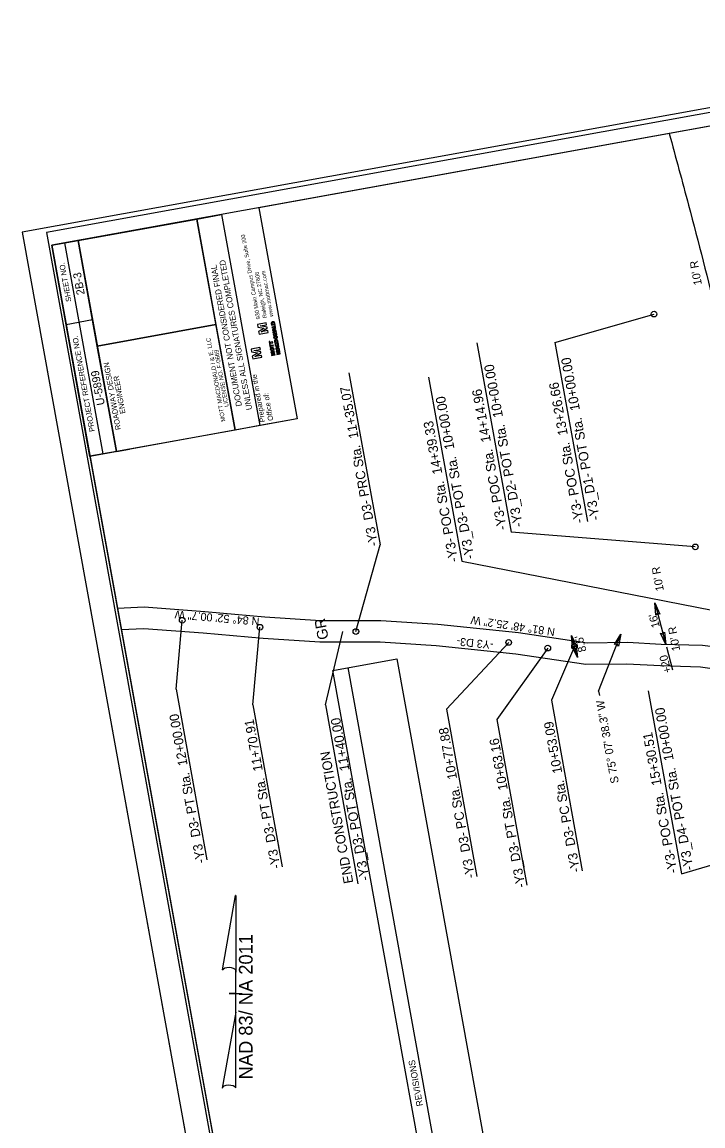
# Model space of a CAD drawing. Extents: x 1620652 to 1621205, y 897765 to 898506.
# Drawn here: x 1620651.7 to 1620905.7, y 898094.1 to 898506 of the extents above; entities that cross this region are included whole.
import ezdxf

# ---------------------------------------------------------------- set-up
doc = ezdxf.new("R2010")
doc.units = 0
for name, color, linetype in [('Exist Roads EOP', 7, 'Continuous'), ('Exist Roads Soil', 7, 'Continuous'), ('Exist Roads Soil Text', 7, 'Continuous'), ('Old_Level_2', 7, 'Continuous'), ('Old_Level_42', 7, 'Continuous'), ('Old_Level_45', 7, 'Continuous'), ('Prop Dimension', 7, 'Continuous'), ('Prop Horizontal Alignment Direction Label', 7, 'Continuous'), ('Prop Horizontal Alignment Station Label', 7, 'Continuous'), ('Prop North Arrow NAD83 for Plan Sheets CELL', 7, 'Continuous'), ('Prop Terminator CELL', 7, 'Continuous'), ('Sheet Block Revision CELL', 7, 'Continuous'), ('Sheet Cutting Line CELL', 7, 'Continuous'), ('Sheet Data Field CELL', 7, 'Continuous'), ('Sheet Layout Plan Border', 7, 'Continuous'), ('Sheet Plan CELL', 7, 'Continuous'), ('Sheet Plot Border Inside CELL', 7, 'Continuous'), ('Sheet Plot Border Outside CELL', 7, 'Continuous'), ('Sheet Sticker Exception Certification CELL', 7, 'Continuous'), ('Sheet Typical CELL', 7, 'Continuous')]:
    doc.layers.add(name, color=color, linetype=linetype)

msp = doc.modelspace()

# ---------------------------------------------------------------- linework, layer by layer
at = {"layer": 'Exist Roads EOP'}
msp.add_spline([(1620893.15, 898464.37), (1620900.36, 898437.64), (1620911.06, 898395.8), (1620918.06, 898367.23), (1620924.24, 898343.43), (1620931.2, 898316.86), (1620938.69, 898288.18), (1620945.98, 898261.48)], degree=3, dxfattribs=at)
at = {"layer": 'Exist Roads Soil'}
for points in [[(1620806.8, 898281.21), (1620785.61, 898282.63), (1620763.04, 898282.63), (1620742.29, 898283.91), (1620719.96, 898285.95), (1620697.28, 898287.65), (1620687.31, 898287.2)], [(1620806.27, 898273.23), (1620785.34, 898274.63), (1620762.79, 898274.63), (1620741.68, 898275.94), (1620719.3, 898277.98), (1620697.17, 898279.64), (1620688.75, 898279.25)], [(1620919.58, 898271.57), (1620905.51, 898273.32), (1620890.18, 898273.76), (1620877.53, 898274.44), (1620862.54, 898274.26), (1620836.86, 898278.11), (1620806.8, 898281.21)], [(1620918.02, 898263.47), (1620904.84, 898265.34), (1620889.85, 898265.76), (1620877.36, 898266.43), (1620861.99, 898266.26), (1620835.87, 898270.17), (1620806.27, 898273.23)]]:
    msp.add_lwpolyline(points, dxfattribs=at)
at = {"layer": 'Old_Level_2'}
for p, q in [((1620742.85, 898393.75), (1620739.5, 898393.15)), ((1620739.5, 898393.15), (1620739.68, 898392.15)), ((1620739.68, 898392.15), (1620741.89, 898391.72)), ((1620741.9, 898391.7), (1620739.98, 898390.52)), ((1620740.56, 898392.61), (1620742.97, 898393.05)), ((1620740.56, 898392.6), (1620740.56, 898392.61)), ((1620743.15, 898392.09), (1620740.56, 898392.6)), ((1620740.97, 898390.41), (1620743.2, 898391.79)), ((1620743.37, 898390.84), (1620740.97, 898390.4)), ((1620741.89, 898391.72), (1620741.92, 898391.73)), ((1620741.93, 898391.7), (1620741.9, 898391.7)), ((1620741.92, 898391.73), (1620741.93, 898391.7)), ((1620742.97, 898393.05), (1620742.85, 898393.75)), ((1620743.2, 898391.79), (1620743.15, 898392.09)), ((1620743.5, 898390.13), (1620743.37, 898390.84)), ((1620744.71, 898393.43), (1620744.82, 898392.85)), ((1620744.82, 898392.85), (1620745.48, 898392.97)), ((1620744.82, 898392.84), (1620744.82, 898392.84)), ((1620745.01, 898393.15), (1620744.95, 898393.47)), ((1620744.96, 898393.47), (1620744.96, 898393.47)), ((1620745.8, 898393.3), (1620745.01, 898393.15)), ((1620745.48, 898392.97), (1620746.1, 898393.08)), ((1620745.75, 898393.62), (1620745.8, 898393.3)), ((1620746.1, 898393.08), (1620745.99, 898393.66)), ((1620739.98, 898390.52), (1620740.16, 898389.52)), ((1620740.16, 898389.52), (1620743.5, 898390.13)), ((1620740.97, 898390.4), (1620740.97, 898390.41)), ((1620745.91, 898386.81), (1620746.02, 898386.23)), ((1620746.2, 898386.53), (1620746.15, 898386.85)), ((1620747, 898386.68), (1620746.2, 898386.53)), ((1620746.94, 898387), (1620747, 898386.68)), ((1620747.29, 898386.46), (1620747.19, 898387.04)), ((1620740.49, 898384.54), (1620737.14, 898383.93)), ((1620737.14, 898383.93), (1620737.32, 898382.94)), ((1620737.32, 898382.94), (1620739.54, 898382.51)), ((1620738.2, 898383.4), (1620740.62, 898383.83)), ((1620738.2, 898383.39), (1620738.2, 898383.4)), ((1620740.79, 898382.88), (1620738.2, 898383.39)), ((1620738.61, 898381.2), (1620740.84, 898382.57)), ((1620740.62, 898383.83), (1620740.49, 898384.54)), ((1620740.84, 898382.57), (1620740.79, 898382.88)), ((1620745.83, 898383.2), (1620744.56, 898382.97)), ((1620744.56, 898382.97), (1620744.62, 898382.59)), ((1620744.62, 898382.59), (1620745.48, 898382.42)), ((1620744.96, 898382.77), (1620745.88, 898382.94)), ((1620744.96, 898382.76), (1620744.96, 898382.77)), ((1620744.96, 898382.76), (1620744.96, 898382.77)), ((1620744.96, 898382.76), (1620744.96, 898382.77)), ((1620745.95, 898382.57), (1620744.96, 898382.76)), ((1620745.88, 898382.94), (1620745.83, 898383.2)), ((1620745.97, 898382.45), (1620745.95, 898382.57)), ((1620746.02, 898386.23), (1620746.68, 898386.35)), ((1620746.51, 898385.9), (1620746.36, 898386.11)), ((1620746.51, 898385.9), (1620746.36, 898386.11)), ((1620747.82, 898383.56), (1620746.54, 898383.33)), ((1620746.54, 898383.33), (1620746.61, 898382.95)), ((1620746.61, 898382.95), (1620747.46, 898382.78)), ((1620746.68, 898386.35), (1620747.29, 898386.46)), ((1620747.46, 898382.78), (1620746.72, 898382.32)), ((1620746.95, 898383.13), (1620747.87, 898383.3)), ((1620746.95, 898383.12), (1620746.95, 898383.13)), ((1620747.93, 898382.93), (1620746.95, 898383.12)), ((1620747.07, 898386.2), (1620747, 898385.96)), ((1620747.07, 898386.2), (1620747, 898385.96)), ((1620747.1, 898382.28), (1620747.96, 898382.8)), ((1620747.87, 898383.3), (1620747.82, 898383.56)), ((1620747.96, 898382.8), (1620747.93, 898382.93)), ((1620739.54, 898382.49), (1620737.62, 898381.3)), ((1620737.62, 898381.3), (1620737.8, 898380.31)), ((1620737.8, 898380.31), (1620741.14, 898380.92)), ((1620741.02, 898381.62), (1620738.61, 898381.19)), ((1620738.61, 898381.19), (1620738.61, 898381.2)), ((1620739.54, 898382.51), (1620739.57, 898382.51)), ((1620739.57, 898382.49), (1620739.54, 898382.49)), ((1620739.57, 898382.51), (1620739.57, 898382.49)), ((1620741.14, 898380.92), (1620741.02, 898381.62)), ((1620745.48, 898382.42), (1620744.74, 898381.96)), ((1620744.74, 898381.96), (1620744.81, 898381.58)), ((1620744.81, 898381.58), (1620746.09, 898381.81)), ((1620745.12, 898381.92), (1620745.97, 898382.45)), ((1620746.04, 898382.08), (1620745.12, 898381.91)), ((1620745.12, 898381.91), (1620745.12, 898381.92)), ((1620745.12, 898381.91), (1620745.12, 898381.92)), ((1620746.09, 898381.81), (1620746.04, 898382.08)), ((1620746.72, 898382.32), (1620746.79, 898381.94)), ((1620746.79, 898381.94), (1620748.07, 898382.17)), ((1620748.02, 898382.44), (1620747.1, 898382.27)), ((1620747.1, 898382.27), (1620747.1, 898382.28)), ((1620748.07, 898382.17), (1620748.02, 898382.44))]:
    msp.add_line(p, q, dxfattribs=at)
for points in [[(1620746.12, 898392.92), (1620745.9, 898392.88), (1620746, 898392.33), (1620744.95, 898392.14), (1620744.99, 898391.87), (1620746.27, 898392.11), (1620746.12, 898392.92)], [(1620746.54, 898390.63), (1620746.48, 898390.94), (1620746.25, 898390.98), (1620746.15, 898391.53), (1620746.35, 898391.65), (1620746.3, 898391.95), (1620745.11, 898391.23), (1620745.17, 898390.89), (1620746.54, 898390.63)], [(1620746.01, 898391.01), (1620745.42, 898391.12), (1620745.93, 898391.42), (1620746.01, 898391.01)], [(1620744.29, 898385.8), (1620744.22, 898386.16), (1620745.26, 898386.35), (1620745.21, 898386.63), (1620744.17, 898386.44), (1620744.1, 898386.81), (1620743.87, 898386.77), (1620744.05, 898385.75), (1620744.29, 898385.8)], [(1620745.9, 898389.44), (1620745.9, 898389.45), (1620746.62, 898390.21), (1620746.57, 898390.47), (1620745.29, 898390.24), (1620745.34, 898389.97), (1620746.15, 898390.12), (1620745.45, 898389.37), (1620745.5, 898389.1), (1620746.77, 898389.33), (1620746.73, 898389.59), (1620745.9, 898389.44)], [(1620744.5, 898384.62), (1620744.43, 898384.99), (1620745.48, 898385.18), (1620745.43, 898385.45), (1620744.38, 898385.26), (1620744.32, 898385.63), (1620744.08, 898385.59), (1620744.26, 898384.58), (1620744.5, 898384.62)], [(1620747.79, 898383.72), (1620747.74, 898384.02), (1620747.51, 898384.07), (1620747.41, 898384.62), (1620747.61, 898384.74), (1620747.55, 898385.04), (1620746.36, 898384.31), (1620746.42, 898383.98), (1620747.79, 898383.72)], [(1620747.26, 898384.09), (1620746.67, 898384.2), (1620747.18, 898384.5), (1620747.26, 898384.09)]]:
    msp.add_lwpolyline(points, dxfattribs=at)
msp.add_arc((1620745.35, 898393.54), 0.65, 10.2599, 190.2599, dxfattribs=at)
for centre, major_axis, ratio, start_param, end_param in [((1620745.35, 898393.54), (0.399, 0.072), 0.900832, 0, 3.141593), ((1620746.55, 898386.93), (0.639, 0.116), 0.930276, 0, 3.141593), ((1620746.55, 898386.92), (0.399, 0.072), 0.900832, 0, 3.141593), ((1620746.79, 898385.62), (-0.639, -0.116), 0.993118, 5.246647, 10.366427), ((1620746.79, 898385.62), (-0.417, -0.075), 0.916103, 5.276876, 10.296021)]:
    msp.add_ellipse(centre, major_axis=major_axis, ratio=ratio, start_param=start_param, end_param=end_param, dxfattribs=at)
for centre, major_axis, ratio in [((1620746.29, 898388.36), (-0.639, -0.116), 0.993118), ((1620746.29, 898388.36), (-0.417, -0.075), 0.916103), ((1620745.04, 898383.96), (-0.639, -0.116), 0.993118), ((1620745.04, 898383.96), (-0.417, -0.075), 0.916103)]:
    msp.add_ellipse(centre, major_axis=major_axis, ratio=ratio, dxfattribs=at)
at = {"layer": 'Old_Level_42'}
msp.add_lwpolyline([(1620740.08, 898436.67), (1620754.33, 898357.93), (1620740.43, 898355.42)], dxfattribs=at)
at = {"layer": 'Prop Dimension'}
for p, q in [((1620887.73, 898289.25), (1620891.84, 898273.75)), ((1620858.9, 898268.88), (1620856.72, 898277.09)), ((1620892.07, 898272.9), (1620894.35, 898264.31))]:
    msp.add_line(p, q, dxfattribs=at)
at = {"layer": 'Prop Horizontal Alignment Station Label'}
for p, q in [((1620850.51, 898386.43), (1620887.48, 898397.02)), ((1620821.37, 898386.32), (1620834.16, 898315.67)), ((1620850.51, 898386.43), (1620862.6, 898319.63)), ((1620773.68, 898375.07), (1620785.29, 898310.94)), ((1620803.35, 898373.51), (1620815.78, 898304.86)), ((1620902.86, 898310.17), (1620834.16, 898315.67)), ((1620776.25, 898278.58), (1620785.29, 898310.94)), ((1620815.78, 898304.86), (1620909.12, 898286.61)), ((1620709.18, 898257.07), (1620711.49, 898282.79)), ((1620737.87, 898251.25), (1620740.47, 898280.19)), ((1620764.87, 898251.2), (1620771.33, 898278.61)), ((1620866.81, 898256.36), (1620875.15, 898277.59)), ((1620833.26, 898274.5), (1620810.09, 898249.6)), ((1620847.83, 898272.4), (1620828.88, 898245.77)), ((1620857.81, 898272.99), (1620849.17, 898252.95)), ((1620709.18, 898257.07), (1620720.7, 898193.43)), ((1620866.81, 898256.36), (1620867.12, 898254.66)), ((1620885.3, 898256.5), (1620897.67, 898188.12)), ((1620737.87, 898251.25), (1620748.8, 898190.83)), ((1620764.87, 898251.2), (1620776.94, 898184.5)), ((1620849.17, 898252.95), (1620860.68, 898189.33)), ((1620810.09, 898249.6), (1620821.39, 898187.21)), ((1620828.88, 898245.77), (1620840.07, 898183.93)), ((1620897.67, 898188.12), (1620932.52, 898198.49))]:
    msp.add_line(p, q, dxfattribs=at)
for centre in [(1620887.48, 898397.02), (1620902.86, 898310.17), (1620711.49, 898282.79), (1620740.47, 898280.19), (1620776.25, 898278.58), (1620833.26, 898274.5), (1620847.83, 898272.4), (1620857.81, 898272.99)]:
    msp.add_circle(centre, 1.05, dxfattribs=at)
at = {"layer": 'Prop North Arrow NAD83 for Plan Sheets CELL'}
for p, q in [((1620726.48, 898152.3), (1620731.41, 898180.11)), ((1620731.44, 898180.11), (1620731.41, 898180.11)), ((1620731.44, 898180.11), (1620731.41, 898180.11)), ((1620731.44, 898180.11), (1620731.43, 898151.43)), ((1620731.42, 898136.55), (1620731.43, 898152.27)), ((1620731.43, 898151.43), (1620731.43, 898152.24)), ((1620729.02, 898143.51), (1620728.99, 898143.51)), ((1620731.15, 898143.51), (1620729.02, 898143.51)), ((1620729.05, 898143.51), (1620733.85, 898143.51)), ((1620731.42, 898136.55), (1620726.4, 898108.2)), ((1620731.44, 898108.32), (1620731.42, 898136.55))]:
    msp.add_line(p, q, dxfattribs=at)
for centre, start_param, end_param in [((1620728.96, 898152), 0.216388, 2.908219), ((1620728.94, 898108.1), 0.201328, 3.141593)]:
    msp.add_ellipse(centre, major_axis=(2.54, -0.02), ratio=0.461098, start_param=start_param, end_param=end_param, dxfattribs=at)
at = {"layer": 'Prop Terminator CELL'}
for points in [[(1620888.13, 898284.7), (1620887.73, 898289.25), (1620889.66, 898285.08), (1620888.74, 898285.43)], [(1620857.12, 898272.54), (1620856.72, 898277.09), (1620858.65, 898272.92), (1620857.73, 898273.28)], [(1620872.78, 898273.68), (1620875.15, 898277.59), (1620874.24, 898273.09), (1620873.7, 898273.91)], [(1620891.44, 898278.29), (1620891.84, 898273.75), (1620889.91, 898277.91), (1620890.83, 898277.56)], [(1620858.49, 898273.43), (1620858.9, 898268.88), (1620856.96, 898273.05), (1620857.88, 898272.7)]]:
    msp.add_lwpolyline(points, close=True, dxfattribs=at)
at = {"layer": 'Sheet Block Revision CELL'}
msp.add_line((1620829.72, 897953.94), (1620773.38, 898265.13), dxfattribs=at)
msp.add_lwpolyline([(1620823.99, 897952.89), (1620767.66, 898264.09), (1620791.49, 898268.42), (1620847.82, 897957.21)], close=True, dxfattribs=at)
at = {"layer": 'Sheet Cutting Line CELL'}
msp.add_line((1620651.74, 898427.6), (1620771.72, 897764.77), dxfattribs=at)
at = {"layer": 'Sheet Layout Plan Border'}
msp.add_lwpolyline([(1621182.95, 897907.07), (1621076.08, 898497.49), (1620740.08, 898436.67), (1620754.33, 898357.93), (1620677.04, 898343.94), (1620769.66, 897832.26)], close=True, dxfattribs=at)
at = {"layer": 'Sheet Plan CELL'}
for p, q in [((1620686.92, 898345.72), (1620672.65, 898424.46)), ((1620686.92, 898345.72), (1620672.65, 898424.46)), ((1620681.98, 898344.82), (1620667.73, 898423.57)), ((1620668.16, 898393.15), (1620678, 898394.95)), ((1620686.92, 898345.72), (1620691.83, 898346.61))]:
    msp.add_line(p, q, dxfattribs=at)
msp.add_lwpolyline([(1620677.04, 898343.93), (1620662.79, 898422.69), (1620672.65, 898424.46), (1620686.92, 898345.72)], close=True, dxfattribs=at)
at = {"layer": 'Sheet Plot Border Inside CELL'}
msp.add_lwpolyline([(1620660.9, 898427.42), (1620779.63, 897771.48), (1621194.92, 897846.65), (1621076.19, 898502.6)], close=True, dxfattribs=at)
at = {"layer": 'Sheet Plot Border Outside CELL'}
msp.add_lwpolyline([(1620651.74, 898427.6), (1620771.72, 897764.77), (1621204.68, 897843.14), (1621084.7, 898505.97)], close=True, dxfattribs=at)
at = {"layer": 'Sheet Sticker Exception Certification CELL'}
for p, q in [((1620731.18, 898353.75), (1620716.93, 898432.48)), ((1620716.94, 898432.48), (1620726.19, 898434.16)), ((1620726.18, 898434.15), (1620740.43, 898355.42)), ((1620740.43, 898355.42), (1620731.18, 898353.75))]:
    msp.add_line(p, q, dxfattribs=at)
at = {"layer": 'Sheet Typical CELL'}
for p, q in [((1620681.98, 898344.84), (1620667.73, 898423.58)), ((1620668.15, 898393.17), (1620677.99, 898394.95)), ((1620679.78, 898385.11), (1620724.04, 898393.12))]:
    msp.add_line(p, q, dxfattribs=at)
for points in [[(1620662.79, 898422.69), (1620769.66, 897832.28), (1621182.94, 897907.09), (1621076.08, 898497.49)], [(1620679.78, 898385.11), (1620672.65, 898424.47), (1620716.93, 898432.49), (1620724.06, 898393.13)], [(1620677.04, 898343.95), (1620662.79, 898422.69), (1620672.65, 898424.47), (1620686.9, 898345.73)], [(1620686.9, 898345.73), (1620679.78, 898385.11), (1620724.06, 898393.13), (1620731.18, 898353.75)]]:
    msp.add_lwpolyline(points, close=True, dxfattribs=at)

# ---------------------------------------------------------------- texts
at = {"layer": 'Exist Roads Soil Text'}
msp.add_text('GR', height=4, rotation=100.2583, dxfattribs=at).set_placement((1620766.09, 898275.91))
at = {"layer": 'Old_Level_2'}
for s, height, p in [('930 Main Campus Drive, Suite 200', 1.5, (1620740.56, 898395.21)), ('Raleigh, NC 27606', 1.5, (1620743.1, 898395.67)), ('www.mottmac.com', 1.5, (1620745.49, 898396.1)), ('Prepared in the ', 1.9274, (1620742.42, 898356.81)), ('Office of:', 1.927, (1620745.47, 898357.37))]:
    msp.add_text(s, height=height, rotation=100.2599, dxfattribs=at).set_placement(p)
at = {"layer": 'Old_Level_45'}
for s, p in [('MOTT MACDONALD I & E, LLC', (1620727.59, 898357.04)), (' LICENSE NO. F-0669', (1620728.89, 898361.91))]:
    msp.add_text(s, height=1.6071, rotation=100.2599, dxfattribs=at).set_placement(p)
at = {"layer": 'Prop Dimension'}
for s, rotation, p in [("10' R", 100.2599, (1620905.35, 898408.09)), ("10' R", 100.2599, (1620891.17, 898293.93)), ("16'", 104.8727, (1620889.64, 898280.41)), ("10' R", 100.2599, (1620897.25, 898271.59)), ("8.5'", 104.8727, (1620862.34, 898271.33)), ('+20', 104.8727, (1620894.04, 898263.53))]:
    msp.add_text(s, height=3, rotation=rotation, dxfattribs=at).set_placement(p)
at = {"layer": 'Prop Horizontal Alignment Direction Label'}
for s, rotation, p in [('N 84%%d 52\' 00.7" W', 175.0519, (1620740.38, 898283.76)), ('N 81%%d 48\' 25.2" W', 171.6046, (1620850.69, 898279.8)), ('-Y3 D3-', 174.1471, (1620827.73, 898274.97)), ('S 75%%d 07\' 38.3" W', 100.2599, (1620874.37, 898222.2))]:
    msp.add_text(s, height=3, rotation=rotation, dxfattribs=at).set_placement(p)
at = {"layer": 'Prop Horizontal Alignment Station Label'}
for s, height, p in [('-Y3_D1- POT Sta.  10+00.00', 3.584, (1620867.27, 898320.4)), ('-Y3_D2- POT Sta.  10+00.00', 3.584, (1620838.56, 898317.84)), ('-Y3- POC Sta.  13+26.66', 3.584, (1620861.27, 898319.31)), ('-Y3_D3- PRC Sta.  11+35.07', 3.5, (1620784.54, 898310.73)), ('-Y3_D3- POT Sta.  10+00.00', 3.584, (1620820.46, 898305.92)), ('-Y3- POC Sta.  14+14.96', 3.584, (1620832.57, 898316.75)), ('-Y3- POC Sta.  14+39.33', 3.584, (1620814.46, 898304.83)), ('-Y3_D3- PT Sta.  12+00.00', 3.5, (1620720.1, 898192.43)), ('-Y3_D4- POT Sta.  10+00.00', 3.584, (1620902.25, 898189.78)), ('-Y3_D3- PT Sta.  11+70.91', 3.5, (1620748.13, 898190.43)), ('-Y3_D3- POT Sta.  11+40.00', 3.584, (1620781.32, 898185.98)), ('-Y3_D3- PC Sta.  10+77.88', 3.5, (1620820.72, 898186.85)), ('-Y3_D3- PC Sta.  10+53.09', 3.5, (1620859.94, 898189.08)), ('-Y3_D3- PT Sta.  10+63.16', 3.5, (1620839.53, 898183.34)), ('-Y3- POC Sta.  15+30.51', 3.584, (1620896.25, 898188.69)), ('END CONSTRUCTION', 3.584, (1620775.32, 898184.89))]:
    msp.add_text(s, height=height, rotation=100.2599, dxfattribs=at).set_placement(p)
at = {"layer": 'Prop North Arrow NAD83 for Plan Sheets CELL'}
msp.add_text('NAD 83/ NA 2011', height=5.1, rotation=89.9808, dxfattribs=at).set_placement((1620737.72, 898111.49))
at = {"layer": 'Sheet Block Revision CELL'}
msp.add_text('REVISIONS', height=2.4, rotation=100.2599, dxfattribs=at).set_placement((1620801.32, 898101.7))
at = {"layer": 'Sheet Data Field CELL'}
for s, p in [('2B-3', (1620675.14, 898404.44)), ('U-5899', (1620682.62, 898363.25))]:
    msp.add_text(s, height=3, rotation=100.26, dxfattribs=at).set_placement(p)
at = {"layer": 'Sheet Plan CELL'}
for s, p in [('SHEET NO.', (1620670.16, 898401.78)), ('PROJECT REFERENCE NO.', (1620678.89, 898353.29))]:
    msp.add_text(s, height=2, rotation=100.26, dxfattribs=at).set_placement(p)
at = {"layer": 'Sheet Sticker Exception Certification CELL'}
for s, p in [('UNLESS ALL SIGNATURES COMPLETED', (1620737.58, 898361.41)), ('DOCUMENT NOT CONSIDERED FINAL', (1620733.75, 898362.78))]:
    msp.add_text(s, height=2.2, rotation=100.2599, dxfattribs=at).set_placement(p)
at = {"layer": 'Sheet Typical CELL'}
for s, p in [('SHEET NO.', (1620670.15, 898401.78)), ('PROJECT REFERENCE NO.', (1620678.89, 898353.3)), ('ROADWAY DESIGN', (1620688.62, 898353.97)), ('ENGINEER', (1620690.32, 898359.99))]:
    msp.add_text(s, height=2, rotation=100.2599, dxfattribs=at).set_placement(p)

doc.saveas('drawing.dxf')
